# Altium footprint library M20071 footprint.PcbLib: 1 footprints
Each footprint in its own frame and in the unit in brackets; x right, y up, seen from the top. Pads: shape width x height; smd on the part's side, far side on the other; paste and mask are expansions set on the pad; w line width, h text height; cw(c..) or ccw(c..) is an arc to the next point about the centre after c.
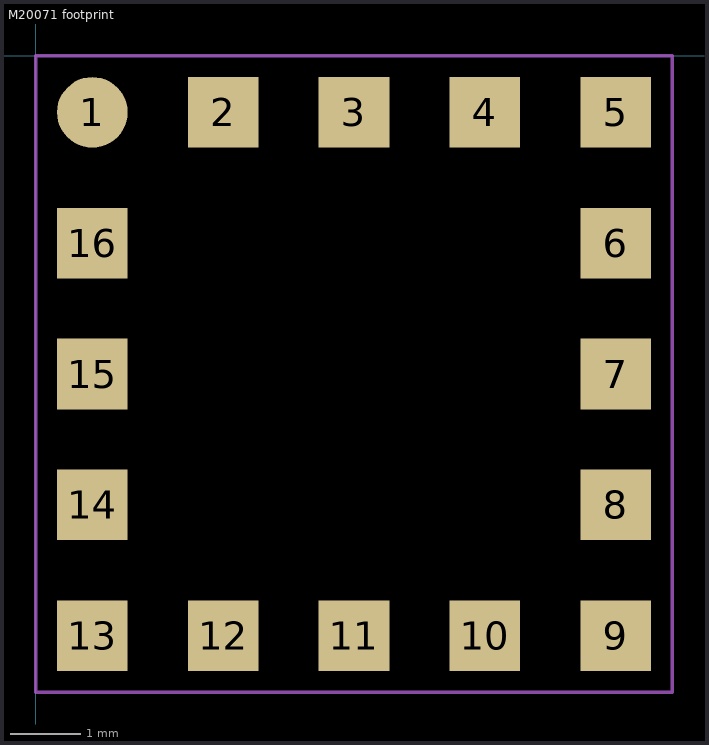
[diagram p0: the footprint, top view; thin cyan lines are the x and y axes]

## M20071 footprint [mm]
pads (16):
  round 1 smd: 1(0.8,-0.8)
  rect 1x1 smd: 2(2.65,-0.8) 3(4.5,-0.8) 4(6.35,-0.8) 5(8.2,-0.8) 6(8.2,-2.65) 7(8.2,-4.5) 8(8.2,-6.35) 9(8.2,-8.2) 10(6.35,-8.2) 11(4.5,-8.2) 12(2.65,-8.2) 13(0.8,-8.2) 14(0.8,-6.35) 15(0.8,-4.5) 16(0.8,-2.65)
Mechanical 1:
  lines w0.05: 0,-9 9,-9 9,0 0,0 0,-9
